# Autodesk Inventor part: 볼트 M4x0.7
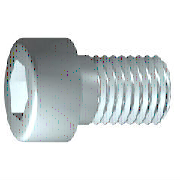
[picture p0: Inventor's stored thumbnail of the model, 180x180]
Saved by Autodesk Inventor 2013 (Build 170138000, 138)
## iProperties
IsCustomPart: 0
Created: 2015-12
Part Number: 볼트 M4x0.7
Material: 강철, 연강
Description: 6각머리 태핑 나사
Document SubType Name: Modeling
Standard: KS B 1003
Designer: mdu
Standards Organization: KS
Language: ko-KR
Size Designation: M 4 x 12
Categories: <MemberInstance><Categories><Category DisplayName="조임쇠" InternalName="e4da775c-781d-43d5-af7c-5136215cf5a6" Mnemonic="FSTN"><Category DisplayName="볼트" InternalN
Density: 7.86 g/cm^3
Mass: 2.23465 g
Surface Area: 3.30853 cm^2
Volume: 0.284306 cm^3
Author: mdu
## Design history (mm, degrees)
sketch "스케치1"
  geometry: L1 (-1, 0)-(12, 0); L2 (12, 0)-(12, 2); L3 (12, 2)-(1.75, 2); L4 (1.75, 2)-(1.32, 2); L5 (1.32, 2)-(0, 2); L6 (0, 2)-(0, 3.5); L7 (0, 3.5)-(-4, 3.5); L8 (-4, 3.5)-(-4, 1.732); L9 (-4, 1.732)-(-2, 1.732); L10 (-2, 1.732)-(-1, 0); L11 (-7.2, 0)-(15.2, 0) reference; L12 (0, -0.7)-(0, 4.2) reference; L13 (1.75, 2)-(0, 2)
  constraints: 22 end point, 6 parallel, 2 collinear, 2 perpendicular, 1 horizontal, 1 point on line
  dimensions: "d1" = 10.25 distance from line of L3.end L2 (= GEL); "d2" = 0.42952 distance of L4.end L3.end (computed from GAL); "d3" = 4 distance between parallel lines of L8 L6 (= KOH); "d4" = 2 distance of L8.end L9.end (= INTI); "d5" = 60 deg angle of L10 L1; "d6" = 4 diameter of L3 L1 (= GD); "d7" = 4 diameter of L5 L1 (= BDM); "d8" = 3.4641 diameter of L9 L1 (= 1.1547 x SW); "d9" = 7 diameter of L7 L1 (= KOD); "d26" = 12 distance between parallel lines of L12 L2 (= NLG)
revolve "본체" sketch "스케치1" stored, may be unused: angle "d10" = 90 deg
sketch "스케치2"
  geometry: L1 (0, -4.9)-(0, 4.9) reference; L2 (-4.9, 0)-(4.9, 0) reference; L3 (1.732, 0)-(0.866, -1.5); L4 (0.866, -1.5)-(-0.866, -1.5); L5 (-0.866, -1.5)-(-1.732, 0); L6 (-1.732, 0)-(-0.866, 1.5); L7 (-0.866, 1.5)-(0.866, 1.5); L8 (0.866, 1.5)-(1.732, 0); 2 further points
  constraints: 12 end point, 1 coincident, 1 horizontal alignment, 1 point on line, 12 other
extrude "슬롯" join sketch "스케치2" stored distance "d11" = 10; taper "d12" = 0 deg
workplane "Work Plane1"
fillet "Fillet2" dims "d30" = 0.1 (= R)
body "Solid1"
fillet "모깎기1" dims "d17" = 0.4 (= RR)
feature "스레드" dims "d13" = 10.25 (= GEL), "d14" = 0
chamfer "모따기1" distance "d15" = 0.42941 (= -0.5 x SPD + 0.5 x GD); stored, may be unused: second distance "d16" = 0.42941 (= GUL), angle "d27" = 45 deg
other parameters: "GD" = 4 (= NND) [user parameter; used in 2 equation terms], "NLG" = 12 [user parameter; used in 1 equation term], "GEL" = 10.25 [user parameter; used in 2 equation terms], "KOD" = 7 [user parameter; used in 1 equation term], "KOH" = 4 [user parameter; used in 1 equation term], "INTI" = 2 [user parameter; used in 1 equation term], "GAL" = 0.42941 (= 0.61345 x PTC) [user parameter; used in 1 equation term], "GUL" = 0.42941 (= 0.61345 x PTC) [user parameter; used in 1 equation term], "BDM" = 4 (= NND) [user parameter; used in 1 equation term], "SW" = 3 [user parameter; used in 2 equation terms], "RR" = 0.4 [user parameter; used in 1 equation term], "SPD" = 3.14117 (= NND - 1.2269 x PTC) [user parameter; used in 1 equation term], "d19" = 0, "d28" = 0, "d29" = 0, "R" = 0.1 [user parameter; used in 1 equation term], "PHH" = 0.2 [user parameter], "GD1" = 3.14117 (= THREADDIA - 1.2269 x PTC) [user parameter], "THREADDIA" = 4 [user parameter; used in 1 equation term], "FAWI" = 45 deg [user parameter], "TPU" = 14.28571 (computed from PTC) [user parameter], "PTC" = 0.7 [user parameter; used in 5 equation terms], "NND" = 4 [user parameter; used in 3 equation terms], "TOA" = 30 deg [user parameter], "E0" = 3.465 (= 1.155 x SW) [user parameter]
